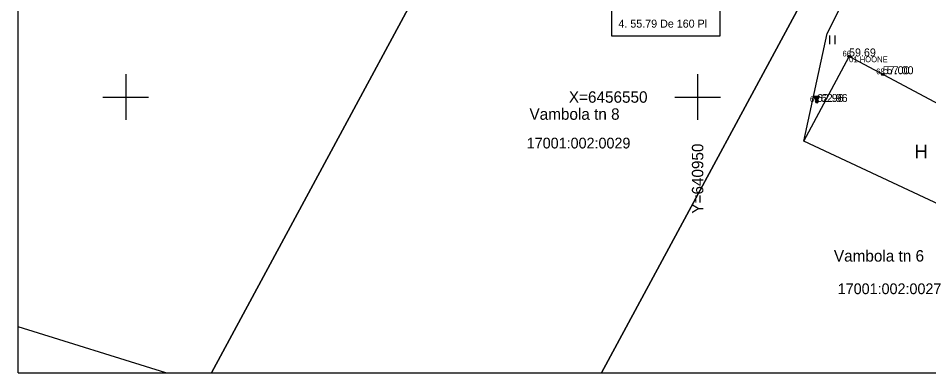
# Model space of a CAD drawing. Extents: x 640891 to 641083, y 6456526 to 6456669.
# Drawn here: x 640890.6 to 640970.2, y 6456525.9 to 6456556.9 of the extents above; entities that cross this region are included whole.
import ezdxf

# ---------------------------------------------------------------- set-up
doc = ezdxf.new("R2010")
doc.units = 0
for name, color, linetype in [('100koma2', 7, 'Continuous'), ('ABIJOONIS', 7, 'Continuous'), ('HALJASTUS', 7, 'Continuous'), ('HOONE', 7, 'Continuous'), ('KORGUS', 7, 'Continuous'), ('MOOTKORG', 7, 'Continuous'), ('MOOTKORG_MUU', 7, 'Continuous'), ('MOOTMPUNKT', 7, 'Continuous'), ('MOOTNR', 7, 'Continuous'), ('MOOTPIIR', 7, 'Continuous'), ('PIIR', 7, 'Continuous'), ('VORK', 7, 'Continuous'), ('VORMISTUS', 7, 'Continuous')]:
    doc.layers.add(name, color=color, linetype=linetype)

msp = doc.modelspace()

# ---------------------------------------------------------------- linework, layer by layer
at = {"layer": 'ABIJOONIS'}
msp.add_lwpolyline([(640942.489, 6456566.685), (640951.949, 6456566.685), (640951.949, 6456555.319), (640942.489, 6456555.319)], close=True, dxfattribs=at)
at = {"layer": 'HALJASTUS'}
for p, q in [((640961.545, 6456555.381), (640961.545, 6456554.619)), ((640962, 6456555.381), (640962, 6456554.619))]:
    msp.add_line(p, q, dxfattribs=at)
at = {"layer": 'HOONE'}
for p in [(640959.29, 6456546.142), (640980.143, 6456544.534)]:
    msp.add_line(p, (640963.241, 6456553.549), dxfattribs=at)
at = {"layer": 'KORGUS'}
for p, q in [((640960.423, 6456549.566), (640960.176, 6456550.053)), ((640960.669, 6456550.053), (640960.176, 6456550.053)), ((640960.185, 6456550.036), (640960.528, 6456549.774)), ((640960.204, 6456550.053), (640960.54, 6456549.797)), ((640960.211, 6456549.985), (640960.517, 6456549.752)), ((640960.236, 6456549.934), (640960.505, 6456549.729)), ((640960.245, 6456550.053), (640960.551, 6456549.82)), ((640960.262, 6456549.883), (640960.494, 6456549.706)), ((640960.287, 6456550.053), (640960.563, 6456549.843)), ((640960.288, 6456549.832), (640960.482, 6456549.684)), ((640960.314, 6456549.78), (640960.471, 6456549.661)), ((640960.328, 6456550.053), (640960.574, 6456549.865)), ((640960.34, 6456549.729), (640960.459, 6456549.638)), ((640960.366, 6456549.678), (640960.448, 6456549.616)), ((640960.369, 6456550.053), (640960.586, 6456549.888)), ((640960.392, 6456549.627), (640960.436, 6456549.593)), ((640960.41, 6456550.053), (640960.597, 6456549.911)), ((640960.423, 6456549.566), (640960.669, 6456550.053)), ((640960.452, 6456550.053), (640960.609, 6456549.933)), ((640960.493, 6456550.053), (640960.62, 6456549.956)), ((640960.534, 6456550.053), (640960.632, 6456549.979)), ((640960.575, 6456550.053), (640960.643, 6456550.001)), ((640960.617, 6456550.053), (640960.655, 6456550.024)), ((640960.658, 6456550.053), (640960.666, 6456550.047)), ((640960.418, 6456549.576), (640960.425, 6456549.57))]:
    msp.add_line(p, q, dxfattribs=at)
msp.add_circle((640966.186, 6456551.992), 0.1, dxfattribs=at)
at = {"layer": 'MOOTMPUNKT'}
for centre in [(640963.241, 6456553.549), (640966.186, 6456551.992), (640960.423, 6456549.566)]:
    msp.add_circle(centre, 0.1, dxfattribs=at)
at = {"layer": 'MOOTPIIR'}
msp.add_lwpolyline([(640976.662, 6456538.007), (640959.29, 6456546.142), (640961.328, 6456555.553), (640965.053, 6456562.959), (640957.364, 6456564.816), (640935.712, 6456572.952), (640933.007, 6456573.069), (640928.881, 6456566.092), (640925.582, 6456561.827), (640921.958, 6456562.765), (640911.417, 6456572.885), (640912.029, 6456574.013), (640921.076, 6456588.216), (640912.945, 6456593.7), (640910.627, 6456595.318), (640915.929, 6456603.505), (640924.706, 6456598.502), (640938.233, 6456631.58)], dxfattribs=at)
at = {"layer": 'PIIR'}
for points in [[(640890.598, 6456557.721), (640910.31, 6456594.28), (640936.74, 6456580.1), (640907.494, 6456525.865)], [(640907.494, 6456525.865), (640936.74, 6456580.1), (640963.18, 6456565.91), (640941.583, 6456525.865)], [(640941.583, 6456525.865), (640963.18, 6456565.91), (640989.66, 6456551.83), (640975.643, 6456525.865)], [(640903.511, 6456525.865), (640890.598, 6456529.899)]]:
    msp.add_lwpolyline(points, dxfattribs=at)
at = {"layer": 'VORK'}
for p, q in [((640900, 6456552), (640900, 6456548)), ((640950, 6456552), (640950, 6456548)), ((640898, 6456550), (640902, 6456550)), ((640948, 6456550), (640952, 6456550))]:
    msp.add_line(p, q, dxfattribs=at)
at = {"layer": 'VORMISTUS'}
for q in [(640890.598, 6456668.776), (641082.733, 6456525.865)]:
    msp.add_line((640890.598, 6456525.865), q, dxfattribs=at)

# ---------------------------------------------------------------- texts
at = {"layer": '100koma2'}
msp.add_text('01 HOONE', height=0.5, dxfattribs=at).set_placement((640963.241, 6456553.049))
at = {"layer": 'ABIJOONIS'}
msp.add_text('4. 55.79 De 160 Pl', height=0.7, dxfattribs=at).set_placement((640943.077, 6456556.071))
at = {"layer": 'HOONE'}
msp.add_text('H', height=1.2, dxfattribs=at).set_placement((640968.961, 6456544.632))
at = {"layer": 'KORGUS'}
for s, p in [('57.00', (640966.536, 6456551.992)), ('62.96', (640960.773, 6456549.566))]:
    msp.add_text(s, height=0.7, dxfattribs=at).set_placement(p)
at = {"layer": 'MOOTKORG'}
for s, p in [('59.69', (640963.241, 6456553.549)), ('57.00', (640966.186, 6456551.992))]:
    msp.add_text(s, height=0.7, dxfattribs=at).set_placement(p)
at = {"layer": 'MOOTKORG_MUU'}
msp.add_text('62.96', height=0.7, dxfattribs=at).set_placement((640960.423, 6456549.566))
at = {"layer": 'MOOTNR'}
for s, p in [('66', (640962.666, 6456553.549)), ('68', (640965.611, 6456551.992)), ('65', (640959.823, 6456549.566))]:
    msp.add_text(s, height=0.5, dxfattribs=at).set_placement(p)
at = {"layer": 'PIIR'}
for s, height, p in [('Vambola tn 8', 1.00002, (640935.299, 6456548.007)), ('17001:002:0029', 0.9375, (640935.06, 6456545.5)), ('Vambola tn 6', 1.00002, (640961.918, 6456535.599)), ('17001:002:0027', 0.9375, (640962.25, 6456532.75))]:
    msp.add_text(s, height=height, dxfattribs=at).set_placement(p)
at = {"layer": 'VORK'}
msp.add_text('X=6456550     ', height=1, dxfattribs=at).set_placement((640938.743, 6456549.5))
msp.add_text('Y=640950     ', height=1, rotation=90, dxfattribs=at).set_placement((640950.5, 6456539.79))

doc.saveas('drawing.dxf')
